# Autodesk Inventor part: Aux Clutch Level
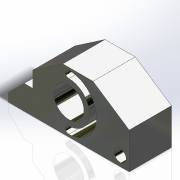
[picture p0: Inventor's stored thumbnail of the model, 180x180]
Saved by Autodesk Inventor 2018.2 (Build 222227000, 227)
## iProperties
Created: 2014-11
Part Number: Aux Clutch Level
Material: Steel
Document SubType Name: Modeling
Designer: Prachaya
Density: 7.85 g/cm^3
Appearance: Chrome - Polished
Mass: 801.585 g
Surface Area: 189.104 cm^2
Volume: 102.113 cm^3
Author: Prachaya
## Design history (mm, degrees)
sketch "Sketch1"
  geometry: L1 (0, 0)-(0, 7); L2 (0, 7)-(13, 20); L3 (13, 20)-(20, 20); L4 (20, 20)-(20, 32.92); L5 (20, 32.92)-(45, 50); L6 (45, 50)-(70, 50); L7 (70, 50)-(100, 30); L8 (100, 30)-(100, 0); L9 (100, 0)-(0, 0); C1 r 12.5 at (50, 25); C2 r 5 at (92.5, 8); A1 r 20 centre (50, 25) between (50, 5) and (50, 45); A2 r 23 centre (50, 25) between (50, 2) and (50, 48); A3 r 17 centre (50, 25) between (50, 8) and (50, 42); A4 r 3 centre (50, 5) between (50, 8) and (50, 2); A5 r 3 centre (50, 45) between (50, 48) and (50, 42)
  constraints: 18 end point, 10 point on circle, 7 centre point, 4 tangent, 2 horizontal, 2 perpendicular, 2 vertical, 2 vertical alignment, 1 coincident
  dimensions: "d0" = 7 distance of L1.start L1.end; "d2" = 20 vertical distance of L1.start L2.end; "d4" = 32.92 vertical distance of L1.start L4.end; "d6" = 50 vertical distance of L1.start L5.end; "d10" = 25 diameter of C1; "d11" = 25 distance from line of L9 C1.centre; "d12" = 50 distance from line of C1.centre L1; "d14" = 10 diameter of C2; "d15" = 8 distance from line of C2.centre L9; "d16" = 7.5 distance from line of C2.centre L8; "d28" = 13 horizontal distance of L1.end L2.end; "d29" = 20 distance between parallel lines of L1 L4; "d30" = 45 distance from line of L1 L5.end; "d31" = 70 horizontal distance of L1.start L6.end; "d32" = 100 distance between parallel lines of L1 L8; "d33" = 30 distance of L7.end L8.end; "d34" = 20 radius of A1; "d35" = 3 radius of A5
extrude "Extrusion1" new body sketch "Sketch1" distance "d17" = 35; taper "d18" = 0 deg
body "Solid1"
